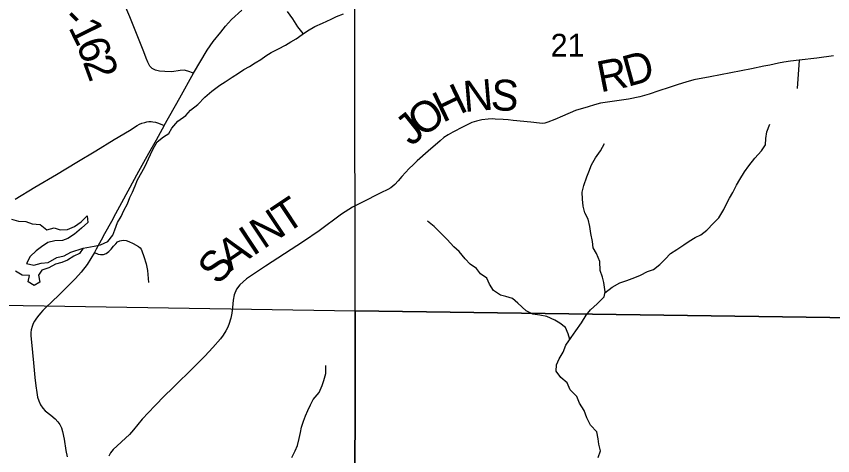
# Model space of a CAD drawing. Extents: x 0 to 191, y 0 to 55.
# Drawn here: x 145.722 to 146.473, y 23.68 to 24.084 of the extents above; entities that cross this region are included whole.
import ezdxf

# ---------------------------------------------------------------- set-up
doc = ezdxf.new("R2010")
doc.units = 0
for name, color, linetype in [('GM_X_Corporation', 7, 'Continuous'), ('GM_X_County_Road', 7, 'Continuous'), ('GM_X_County_Road_Text', 7, 'Continuous'), ('GM_X_Major_Lake', 7, 'Continuous'), ('GM_X_Minor_River', 7, 'Continuous'), ('GM_X_Section_Text', 7, 'Continuous'), ('GM_X_State_Route', 7, 'Continuous'), ('GM_X_Township_Road', 7, 'Continuous'), ('GM_X_Township_Road_Text', 7, 'Continuous')]:
    doc.layers.add(name, color=color, linetype=linetype)

msp = doc.modelspace()

# ---------------------------------------------------------------- linework, layer by layer
at = {"layer": 'GM_X_Corporation'}
for points in [[(146.03321, 24.31897), (146.54032, 24.31446), (146.53796, 24.10543), (146.53621, 23.80622), (146.0338, 23.81325)], [(145.53727, 23.82138), (146.0338, 23.81325), (146.03304, 23.3384), (145.53282, 23.34555)], [(146.53621, 23.80622), (146.53556, 23.59664), (146.53466, 23.33382), (146.03304, 23.3384), (146.0338, 23.81325)]]:
    msp.add_lwpolyline(points, close=True, dxfattribs=at)
at = {"layer": 'GM_X_County_Road'}
msp.add_lwpolyline([(146.47391, 24.04773), (146.4586, 24.04556), (146.44245, 24.04381), (146.43435, 24.04286), (146.4281, 24.0419), (146.42328, 24.0409), (146.41534, 24.03926), (146.40972, 24.0382), (146.39849, 24.03571), (146.37943, 24.03227), (146.36042, 24.02861), (146.34549, 24.02565), (146.33802, 24.02353), (146.33092, 24.02141), (146.32277, 24.01882), (146.31334, 24.01564), (146.30432, 24.01251), (146.29579, 24.01002), (146.28537, 24.0079), (146.26801, 24.00558), (146.25943, 24.00415), (146.25387, 24.00282), (146.24824, 24.00095), (146.2365, 23.9975), (146.22459, 23.99234), (146.21765, 23.98937), (146.21113, 23.98683), (146.20833, 23.98598), (146.20605, 23.98566), (146.20324, 23.98588), (146.1953, 23.98667), (146.17904, 23.98831), (146.1747, 23.98879), (146.16993, 23.98921), (146.16273, 23.98964), (146.15987, 23.98974), (146.15601, 23.98958), (146.15039, 23.98884), (146.14552, 23.98784), (146.14118, 23.9864), (146.13318, 23.98243), (146.1237, 23.97767), (146.1192, 23.97518), (146.11549, 23.97274), (146.11184, 23.96972), (146.10098, 23.96014), (146.09092, 23.9513), (146.087, 23.94769), (146.08346, 23.94404), (146.07673, 23.93668), (146.07339, 23.93271), (146.07027, 23.92953), (146.06852, 23.92784), (146.06646, 23.92651), (146.06391, 23.92498), (146.0574, 23.92191), (146.03998, 23.91306), (146.0314, 23.90851), (146.02107, 23.90205), (146.00063, 23.88701), (145.98607, 23.87716), (145.95128, 23.85449), (145.93391, 23.84258), (145.9275, 23.83723), (145.92453, 23.8331), (145.92252, 23.82791), (145.92162, 23.82298), (145.92083, 23.81642), (145.92019, 23.81128), (145.91929, 23.80651), (145.91754, 23.80069), (145.91627, 23.79762), (145.91479, 23.79491), (145.91219, 23.79094), (145.90992, 23.7875), (145.90287, 23.77961), (145.8953, 23.77167), (145.88656, 23.76272), (145.86543, 23.74196), (145.8585, 23.73544), (145.84933, 23.72591), (145.83784, 23.71357), (145.8299, 23.70394), (145.82603, 23.69949), (145.81115, 23.68582), (145.80861, 23.68265), (145.80702, 23.67952)], dxfattribs=at)
at = {"layer": 'GM_X_Major_Lake'}
msp.add_lwpolyline([(145.71762, 23.89759), (145.72406, 23.89573), (145.73069, 23.89539), (145.73657, 23.89316), (145.74395, 23.89282), (145.75004, 23.88793), (145.75684, 23.88968), (145.76234, 23.88782), (145.76915, 23.88805), (145.77557, 23.89094), (145.7816, 23.89515), (145.78724, 23.90069), (145.78785, 23.89443), (145.78201, 23.88946), (145.77561, 23.88392), (145.7692, 23.8797), (145.76429, 23.87797), (145.75729, 23.87773), (145.75105, 23.87617), (145.74502, 23.87215), (145.74012, 23.86833), (145.73467, 23.86317), (145.7313, 23.85689), (145.73793, 23.85522), (145.74473, 23.85716), (145.75135, 23.85777), (145.75909, 23.86219), (145.76589, 23.86375), (145.77211, 23.8672), (145.78344, 23.87107), (145.78007, 23.86592), (145.77498, 23.86343), (145.76894, 23.85978), (145.76384, 23.85766), (145.75799, 23.85611), (145.75176, 23.85284), (145.74534, 23.85072), (145.74234, 23.84596), (145.7437, 23.8397), (145.73842, 23.83664), (145.73272, 23.84001), (145.7342, 23.8459), (145.7272, 23.84605), (145.72112, 23.84962)], dxfattribs=at)
at = {"layer": 'GM_X_Minor_River'}
for points in [[(145.8401, 23.9456), (145.84533, 23.95715), (145.84798, 23.96229), (145.85157, 23.96857), (145.85725, 23.97333), (145.86217, 23.97639), (145.865, 23.98133), (145.87068, 23.98762), (145.87807, 23.99296), (145.88223, 23.99791), (145.88886, 24.00306), (145.89529, 24.00973), (145.90173, 24.01544), (145.9093, 24.02079), (145.91404, 24.02384), (145.92067, 24.02804), (145.92635, 24.03186), (145.93128, 24.0351), (145.93639, 24.03797), (145.9417, 24.04121), (145.94681, 24.04427), (145.95155, 24.0477), (145.95647, 24.05075), (145.96329, 24.05419), (145.96973, 24.05763), (145.97466, 24.06069), (145.9794, 24.06336), (145.98508, 24.06756), (145.99, 24.0708), (145.99663, 24.07462), (146.00365, 24.07769), (146.01179, 24.08151), (146.01672, 24.084), (146.02298, 24.0863)], [(145.98604, 24.06819), (145.98107, 24.07457), (145.97631, 24.08178), (145.97155, 24.0886)], [(146.26359, 23.82989), (146.27023, 23.8351), (146.27743, 23.83912), (146.28387, 23.84123), (146.29127, 23.8441), (146.29619, 23.8462), (146.30283, 23.84945), (146.30832, 23.85137), (146.3142, 23.85575), (146.31912, 23.8609), (146.32385, 23.86604), (146.32991, 23.86967), (146.33635, 23.87405), (146.34108, 23.8773), (146.34677, 23.88073), (146.3517, 23.88322), (146.35738, 23.88741), (146.36362, 23.89389), (146.36835, 23.89884), (146.37289, 23.90645), (146.37553, 23.91159), (146.37837, 23.91691), (146.38139, 23.92224), (146.38479, 23.92871), (146.38781, 23.93403), (146.39197, 23.94126), (146.39594, 23.94678), (146.40161, 23.95383), (146.40767, 23.9603), (146.41145, 23.96601), (146.41181, 23.9719), (146.41256, 23.97798), (146.4152, 23.98502)], [(146.24807, 23.89769), (146.24521, 23.90338), (146.24368, 23.90964), (146.2431, 23.91609), (146.2427, 23.92236), (146.2442, 23.92863), (146.24703, 23.93642), (146.24873, 23.94118), (146.25137, 23.94764), (146.25496, 23.95392), (146.25949, 23.96058), (146.26327, 23.96705)], [(145.78344, 23.87107), (145.79354, 23.87268), (145.7994, 23.87385), (145.80601, 23.87692), (145.8109, 23.88302), (145.81258, 23.88777), (145.81519, 23.89443), (145.81838, 23.90014), (145.82081, 23.90546), (145.82418, 23.91174), (145.82642, 23.91745), (145.82886, 23.92239), (145.83129, 23.92829), (145.83334, 23.9338), (145.8401, 23.9456)], [(146.2575, 23.67844), (146.25938, 23.68452), (146.25785, 23.69059), (146.25746, 23.69571), (146.25612, 23.70217), (146.25041, 23.70822), (146.24698, 23.71504), (146.2445, 23.72149), (146.24031, 23.72831), (146.23764, 23.73438), (146.23155, 23.74062), (146.22888, 23.74707), (146.22299, 23.75199), (146.21861, 23.75767), (146.21917, 23.76355), (146.22162, 23.76907), (146.22502, 23.77534), (146.22748, 23.78181), (146.23258, 23.78866), (146.23693, 23.79475), (146.24204, 23.80236), (146.24638, 23.80921), (146.25017, 23.81435), (146.25642, 23.81968), (146.26285, 23.82616), (146.26379, 23.83091), (146.26263, 23.83945), (146.26129, 23.84419), (146.25919, 23.85045), (146.25879, 23.8588), (146.25574, 23.86601), (146.25269, 23.87131), (146.25211, 23.87701), (146.25057, 23.88441), (146.24961, 23.89086), (146.24807, 23.89769)], [(146.2314, 23.78707), (146.22973, 23.79226), (146.22725, 23.79794), (146.22212, 23.80191), (146.21737, 23.80456), (146.21015, 23.80814), (146.2037, 23.80945), (146.19724, 23.81038), (146.19098, 23.81339), (146.18356, 23.8204), (146.17862, 23.82475), (146.17235, 23.82643), (146.16761, 23.82756), (146.16114, 23.83209), (146.15753, 23.83797), (146.15486, 23.84328), (146.14916, 23.84724), (146.14535, 23.85217), (146.13965, 23.85614), (146.13508, 23.86125), (146.12957, 23.86788), (146.12443, 23.87223), (146.11854, 23.87885), (146.10636, 23.89097), (146.10047, 23.89569)], [(145.97538, 23.67829), (145.9784, 23.68457), (145.98067, 23.68932), (145.98236, 23.69597), (145.98349, 23.70148), (145.98442, 23.70642), (145.98612, 23.71193), (145.988, 23.71668), (145.99027, 23.72162), (145.99272, 23.72694), (145.99518, 23.73189), (146.00048, 23.73817), (146.0035, 23.74463), (146.005, 23.74938), (146.00689, 23.75566), (146.00687, 23.76287)]]:
    msp.add_lwpolyline(points, dxfattribs=at)
at = {"layer": 'GM_X_State_Route'}
for points in [[(145.85785, 23.98362), (145.87228, 24.00907), (145.88499, 24.03188), (145.89748, 24.05303), (145.90301, 24.06103), (145.91004, 24.06963), (145.91452, 24.07494), (145.92006, 24.08107), (145.9294, 24.08982)], [(145.72083, 23.91609), (145.73885, 23.92695), (145.75889, 23.93878), (145.77763, 23.95011), (145.7951, 23.96048), (145.81193, 23.97076), (145.82597, 23.97924), (145.83326, 23.98364), (145.83542, 23.98483), (145.83752, 23.98577), (145.8402, 23.98662), (145.84191, 23.98706), (145.84393, 23.98726), (145.84589, 23.98731), (145.84766, 23.9872), (145.8499, 23.98684), (145.85197, 23.98626), (145.85438, 23.98541), (145.85785, 23.98362)], [(145.85785, 23.98362), (145.85056, 23.97025), (145.84365, 23.95804), (145.83446, 23.94128), (145.82465, 23.92322), (145.81884, 23.91267), (145.81319, 23.90238), (145.80942, 23.89532), (145.8031, 23.88409), (145.80012, 23.87836), (145.79549, 23.87), (145.79392, 23.86708), (145.79042, 23.86136), (145.78701, 23.85599), (145.78147, 23.84884), (145.77633, 23.84295), (145.76978, 23.83616), (145.76609, 23.83267), (145.76118, 23.8278), (145.7549, 23.82187), (145.74901, 23.81642), (145.7463, 23.81363), (145.74415, 23.81116), (145.74132, 23.8077), (145.73983, 23.80562), (145.73881, 23.80394), (145.73759, 23.80162), (145.73649, 23.79875), (145.73571, 23.79589), (145.73543, 23.79334), (145.73543, 23.79047), (145.7368, 23.77489), (145.73767, 23.76547), (145.73912, 23.75189), (145.73998, 23.74431), (145.74077, 23.73815), (145.74152, 23.73403), (145.74257, 23.73038), (145.74415, 23.72696), (145.74634, 23.72382), (145.74858, 23.72147), (145.75368, 23.71746), (145.75777, 23.71393), (145.76016, 23.71122), (145.76193, 23.70871), (145.76338, 23.70569), (145.76456, 23.70239), (145.76593, 23.69529), (145.76766, 23.68473), (145.76864, 23.67915)]]:
    msp.add_lwpolyline(points, dxfattribs=at)
at = {"layer": 'GM_X_Township_Road'}
msp.add_line((146.44245, 24.04381), (146.44054, 24.01769), dxfattribs=at)
for points in [[(145.88499, 24.03188), (145.87969, 24.03375), (145.87655, 24.03449), (145.87281, 24.03434), (145.86496, 24.03322), (145.85853, 24.03345), (145.85359, 24.03382), (145.85013, 24.03463), (145.84702, 24.03629), (145.84477, 24.03838), (145.84287, 24.04206), (145.84155, 24.04574), (145.83924, 24.05138), (145.83495, 24.06223), (145.83084, 24.0729), (145.82655, 24.0838), (145.82261, 24.09233)], [(145.79392, 23.86708), (145.79725, 23.86548), (145.79926, 23.86513), (145.80204, 23.86521), (145.80455, 23.86611), (145.80703, 23.86784), (145.80926, 23.86992), (145.81138, 23.87267), (145.8134, 23.87495), (145.8152, 23.87665), (145.81712, 23.8776), (145.81888, 23.8781), (145.82087, 23.87828), (145.8231, 23.87803), (145.82543, 23.87707), (145.82954, 23.8752), (145.83438, 23.8724), (145.83583, 23.87131), (145.83682, 23.87007), (145.83753, 23.86858), (145.83923, 23.86313), (145.84128, 23.85662), (145.8427, 23.85046), (145.84362, 23.83946)]]:
    msp.add_lwpolyline(points, dxfattribs=at)

# ---------------------------------------------------------------- texts
at = {"layer": 'GM_X_County_Road_Text'}
for s, rotation, p in [('D', 15.34204, (146.28458, 24.01914)), ('R', 11.07953, (146.25947, 24.01414)), ('N', 4.84714, (146.13426, 23.9961)), ('S', 356.50073, (146.15808, 23.9982)), ('H', 25.67713, (146.11435, 23.98598)), ('O', 35.67572, (146.09517, 23.97207)), ('J', 38.48061, (146.08502, 23.964)), ('T', 33.61826, (145.97008, 23.88343)), ('N', 33.61732, (145.94926, 23.86959)), ('I', 33.62078, (145.93955, 23.86313)), ('A', 34.11846, (145.9189, 23.84915)), ('S', 48.91375, (145.90776, 23.83598))]:
    msp.add_text(s, height=0.02841, rotation=rotation, dxfattribs=at).set_placement(p)
at = {"layer": 'GM_X_Section_Text'}
msp.add_text('21', height=0.020928, rotation=0.00001, dxfattribs=at).set_placement((146.21365, 24.04711))
at = {"layer": 'GM_X_Township_Road_Text'}
for s, rotation, p in [('-', 313.98422, (145.76268, 24.08051)), ('1', 296.39283, (145.76946, 24.07399)), ('6', 289.52116, (145.77689, 24.05915)), ('2', 290.21455, (145.78286, 24.0423))]:
    msp.add_text(s, height=0.02841, rotation=rotation, dxfattribs=at).set_placement(p)

doc.saveas('drawing.dxf')
